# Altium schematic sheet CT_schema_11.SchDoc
size 742 x 377 mm
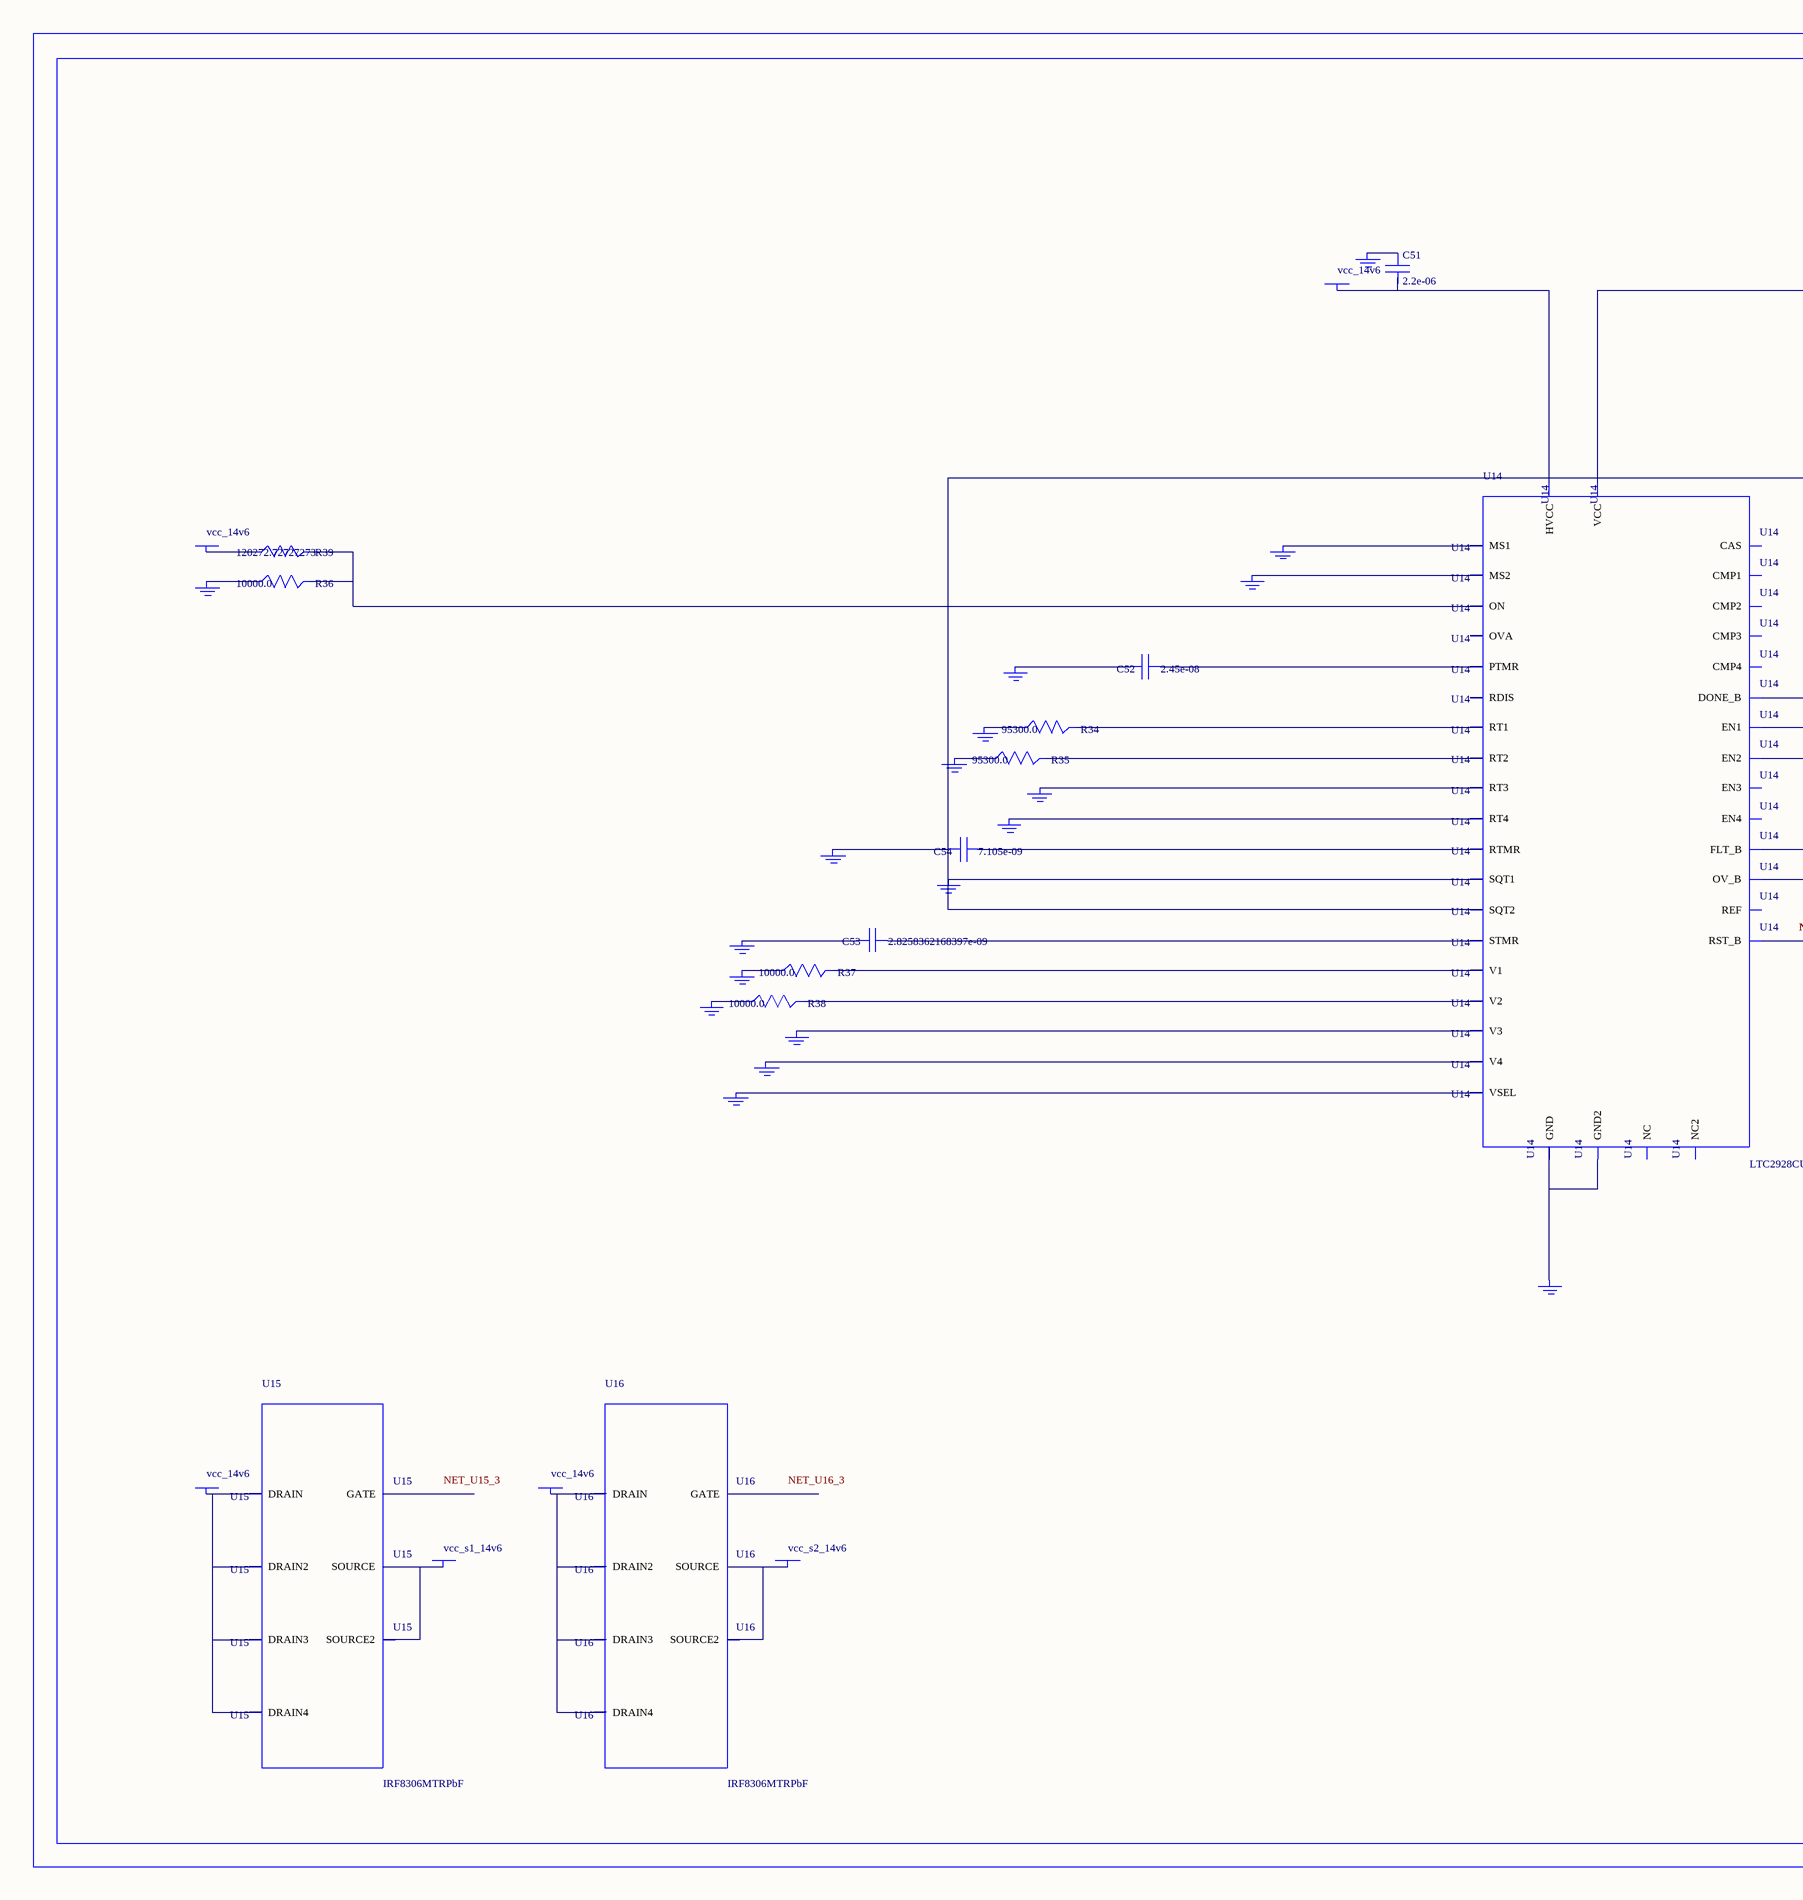
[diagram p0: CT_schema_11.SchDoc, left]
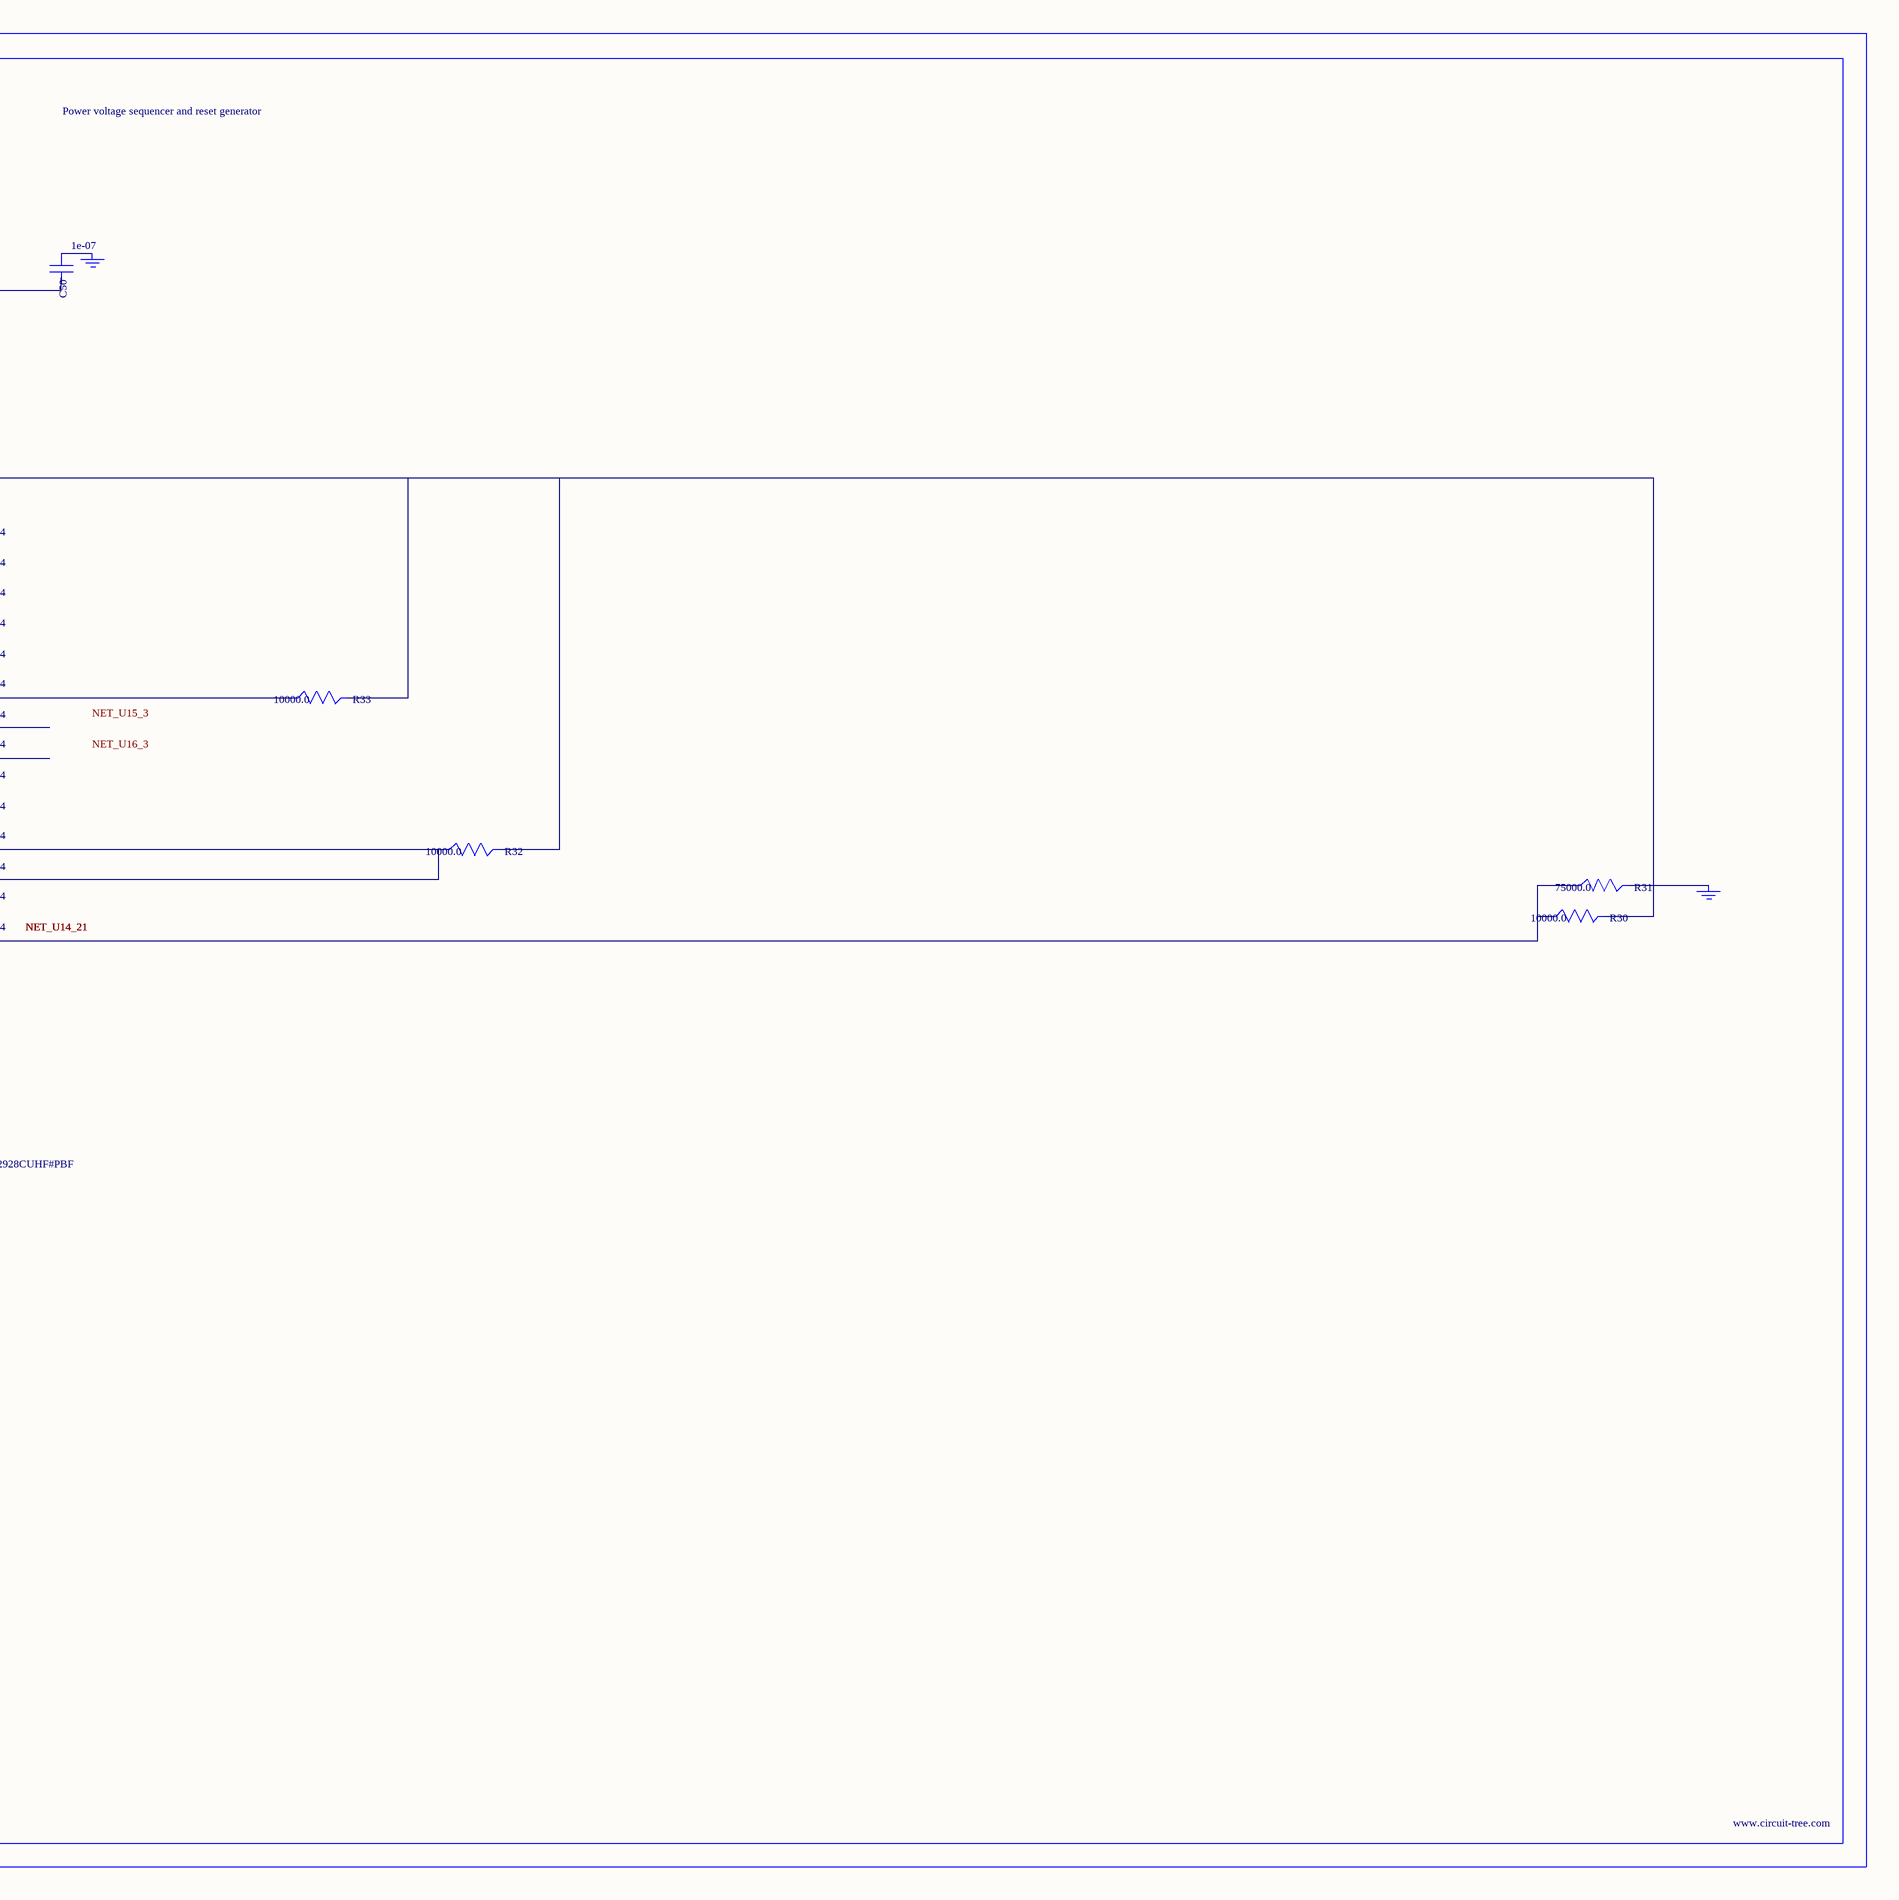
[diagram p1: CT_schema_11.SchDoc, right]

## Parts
BORDER10  (no value)
C50  1e-07  [C0402]
C51  2.2e-06  [C0603]
C52  2.45e-08  [R0603]
C53  2.8258362168397e-09  [R0603]
C54  7.105e-09  [R0603]
GND_INSTANCE_10_0  (no value)
GND_INSTANCE_10_1  (no value)
GND_INSTANCE_10_2  (no value)
GND_INSTANCE_10_3  (no value)
GND_INSTANCE_10_4  (no value)
GND_INSTANCE_10_5  (no value)
GND_INSTANCE_10_6  (no value)
GND_INSTANCE_10_7  (no value)
GND_INSTANCE_10_8  (no value)
GND_INSTANCE_10_9  (no value)
GND_INSTANCE_10_10  (no value)
GND_INSTANCE_10_11  (no value)
GND_INSTANCE_10_12  (no value)
GND_INSTANCE_10_13  (no value)
GND_INSTANCE_10_14  (no value)
GND_INSTANCE_10_15  (no value)
GND_INSTANCE_10_16  (no value)
GND_INSTANCE_10_17  (no value)
GND_INSTANCE_10_18  (no value)
GND_INSTANCE_10_19  (no value)
POWER_INSTANCE_10_0  vcc_14v6
POWER_INSTANCE_10_1  vcc_14v6
POWER_INSTANCE_10_2  vcc_14v6
POWER_INSTANCE_10_3  vcc_s1_14v6
POWER_INSTANCE_10_4  vcc_14v6
POWER_INSTANCE_10_5  vcc_s2_14v6
R30  10000.0  [R0603]
R31  75000.0  [R0603]
R32  10000.0  [R0603]
R33  10000.0  [R0603]
R34  95300.0  [R0603]
R35  95300.0  [R0603]
R36  10000.0  [R0603]
R37  10000.0  [R0603]
R38  10000.0  [R0603]
R39  120272.72727273  [R0603]
U14  LTC2928CUHF#PBF  [QFN-38_UHF]
U15  IRF8306MTRPbF  [IRF8306MTRPBF]
U16  IRF8306MTRPbF  [IRF8306MTRPBF]

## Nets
NetC50_1: C50.1 GND_INSTANCE_10_10.0(GND)
NetC50_2: C50.2 C54.2 GND_INSTANCE_10_5.0(GND) GND_INSTANCE_10_15.0(GND) R30.2 R32.2 R33.2 U14.10(SQT1) U14.11(SQT2) U14.22(VCC)
NetC51_1: C51.1 GND_INSTANCE_10_11.0(GND)
NetC51_2: C51.2 POWER_INSTANCE_10_1.0(PWR) U14.23(HVCC)
NetC52_1: C52.1 U14.27(PTMR)
NetC52_2: C52.2 GND_INSTANCE_10_14.0(GND)
NetC53_1: C53.1 U14.26(STMR)
NetC53_2: C53.2 GND_INSTANCE_10_13.0(GND)
NetC54_1: C54.1 U14.28(RTMR)
NetGND_INSTANCE_10_0_0: GND_INSTANCE_10_0.0(GND) R37.1
NetGND_INSTANCE_10_1_0: GND_INSTANCE_10_1.0(GND) R34.1
NetGND_INSTANCE_10_2_0: GND_INSTANCE_10_2.0(GND) R35.1
NetGND_INSTANCE_10_3_0: GND_INSTANCE_10_3.0(GND) U14.8(RT3)
NetGND_INSTANCE_10_4_0: GND_INSTANCE_10_4.0(GND) U14.9(RT4)
NetGND_INSTANCE_10_6_0: GND_INSTANCE_10_6.0(GND) U14.12(MS1)
NetGND_INSTANCE_10_7_0: GND_INSTANCE_10_7.0(GND) U14.13(MS2)
NetGND_INSTANCE_10_8_0: GND_INSTANCE_10_8.0(GND) R36.1
NetGND_INSTANCE_10_9_0: GND_INSTANCE_10_9.0(GND) R31.2
NetGND_INSTANCE_10_12_0: GND_INSTANCE_10_12.0(GND) U14.25(VSEL)
NetGND_INSTANCE_10_16_0: GND_INSTANCE_10_16.0(GND) U14.30(V4)
NetGND_INSTANCE_10_17_0: GND_INSTANCE_10_17.0(GND) U14.32(V3)
NetGND_INSTANCE_10_18_0: GND_INSTANCE_10_18.0(GND) R38.1
NetGND_INSTANCE_10_19_0: GND_INSTANCE_10_19.0(GND) U14.24(GND) U14.39(GND2)
NetPOWER_INSTANCE_10_0_0: POWER_INSTANCE_10_0.0(PWR) R39.1
NetPOWER_INSTANCE_10_2_0: POWER_INSTANCE_10_2.0(PWR) U15.1(DRAIN) U15.2(DRAIN2) U15.6(DRAIN3) U15.7(DRAIN4)
NetPOWER_INSTANCE_10_3_0: POWER_INSTANCE_10_3.0(PWR) U15.4(SOURCE) U15.5(SOURCE2)
NetPOWER_INSTANCE_10_4_0: POWER_INSTANCE_10_4.0(PWR) U16.1(DRAIN) U16.2(DRAIN2) U16.6(DRAIN3) U16.7(DRAIN4)
NetPOWER_INSTANCE_10_5_0: POWER_INSTANCE_10_5.0(PWR) U16.4(SOURCE) U16.5(SOURCE2)
NetR30_1: R30.1 R31.1 U14.21(RST_B)
NetR32_1: R32.1 U14.19(FLT_B) U14.20(OV_B)
NetR33_1: R33.1 U14.18(DONE_B)
NetR34_2: R34.2 U14.6(RT1)
NetR35_2: R35.2 U14.7(RT2)
NetR36_2: R36.2 R39.2 U14.16(ON)
NetR37_2: R37.2 U14.3(V1)
NetR38_2: R38.2 U14.38(V2)

Not connected (* = marked no-connect by the designer): U14 1(OVA) 2(EN1) 4(NC) 5(REF) 14(RDIS) 15(CAS) 17(NC2) 29(EN4) 31(EN3) 33(CMP3) 34(CMP4) 35(CMP1) 36(CMP2) 37(EN2); U15 3(GATE); U16 3(GATE)

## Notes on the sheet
- Labels drawn without touching a wire or pin: NET_U15_3, NET_U16_3

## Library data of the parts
BORDER10 = BORDER_PAGE10
C50 = C0402C104K3RACTU
C51 = GRM188R61H225KE1115D
C52 = C52
C53 = C53
C54 = C54
GND_INSTANCE_10_0-GND_INSTANCE_10_19 = GND
POWER_INSTANCE_10_0-POWER_INSTANCE_10_5 = PWR
R30 R32 R33 R36-R38 = RC0603JR-0710KL
R31 = RC0603JR-0775KL
R34 R35 = RC0603FR-0795K3L
R39 = R39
